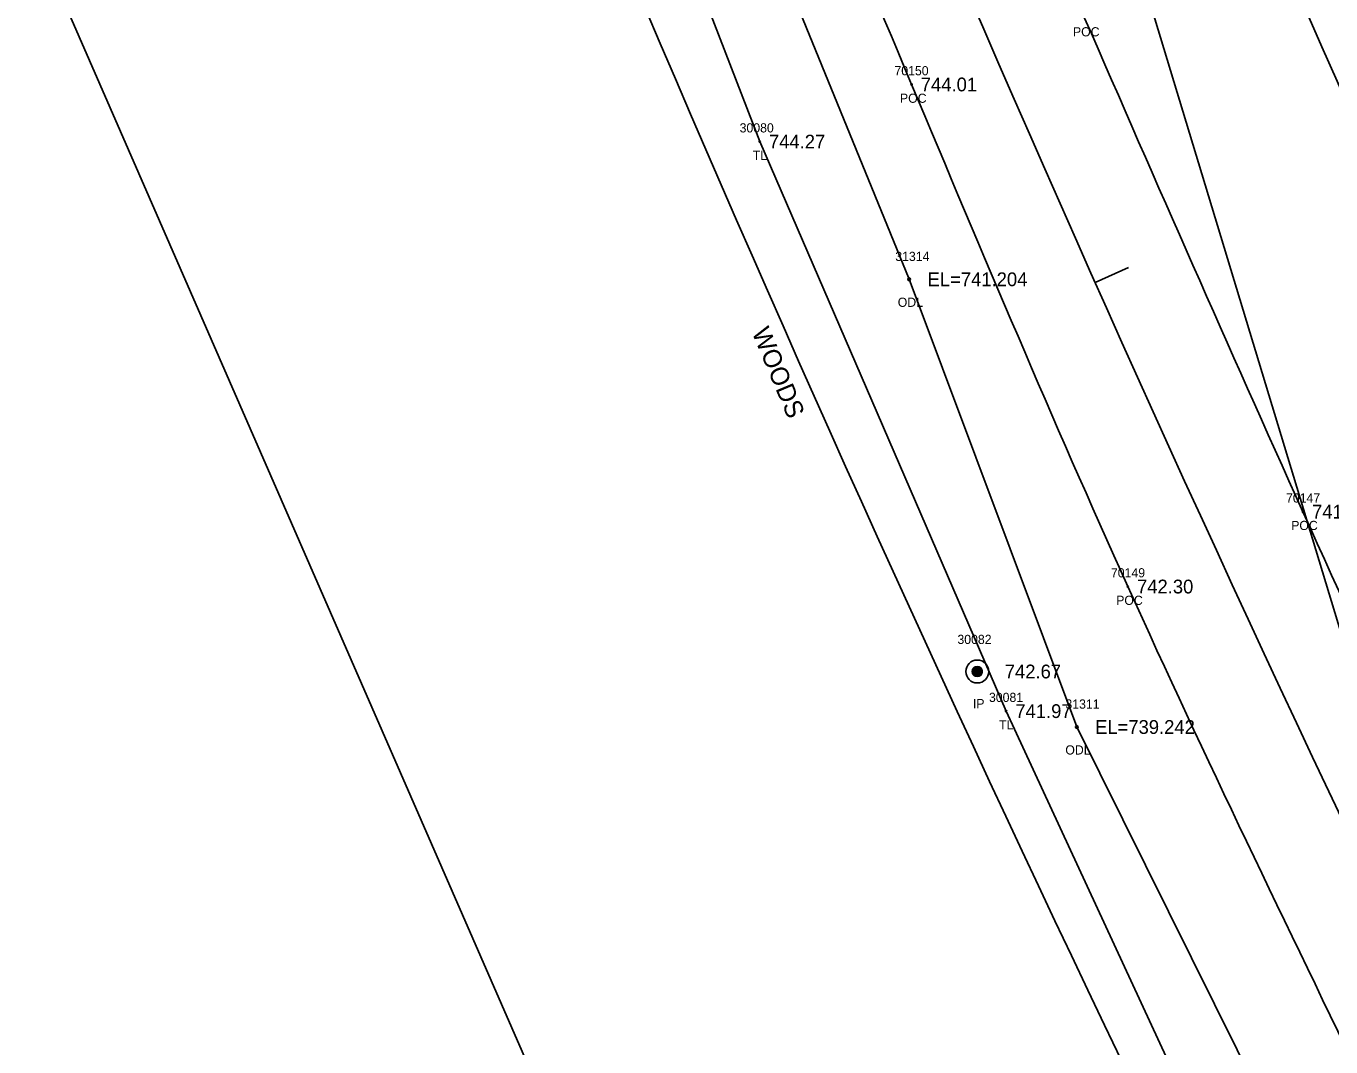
# Model space of a CAD drawing. Extents: x 1375131 to 1378678, y 999028 to 1004053.
# Drawn here: x 1376731 to 1376873.2, y 1002476.7 to 1002588 of the extents above; entities that cross this region are included whole.
import ezdxf

# ---------------------------------------------------------------- set-up
doc = ezdxf.new("R2010")
doc.units = 0
for name, color, linetype in [('RD_EX_DV_Prop', 7, 'Continuous'), ('RD_EX_DV_Prop_txCode', 7, 'Continuous'), ('RD_EX_DV_PropPin', 7, 'Continuous'), ('RD_EX_H2O', 7, 'Continuous'), ('RD_EX_H2O_txCode', 7, 'Continuous'), ('RD_EX_Road', 7, 'Continuous'), ('RD_EX_Road_txCode', 7, 'Continuous'), ('RD_EX_RW', 7, 'Continuous'), ('RD_EX_SU_Elec', 7, 'Continuous'), ('RD_EX_TX_DV_Prop_ELEV', 7, 'Continuous'), ('RD_EX_TX_H2O_ELEV', 7, 'Continuous'), ('RD_EX_TX_Road_ELEV', 7, 'Continuous'), ('RD_EX_TX_VEG_ELEV', 7, 'Continuous'), ('RD_EX_VEG', 7, 'Continuous'), ('RD_EX_VEG_txCode', 7, 'Continuous'), ('RD_HC_Cl', 7, 'Continuous'), ('RD_HC_Data_Tic', 7, 'Continuous'), ('RD_SMD_Locator', 7, 'Continuous'), ('RD_TX_Misc2', 7, 'Continuous')]:
    doc.layers.add(name, color=color, linetype=linetype)

msp = doc.modelspace()

# ---------------------------------------------------------------- linework, layer by layer
at = {"layer": 'RD_EX_DV_Prop'}
msp.add_lwpolyline([(1376724.42, 1002117.06), (1376637.57, 1002230.63), (1376389.38, 1002558.79), (1376664.3, 1002769.81), (1376707.09, 1002654.77), (1376824.56, 1002385.67), (1376921.89, 1002216.69), (1376947.76, 1002098.6)], dxfattribs=at)
at = {"layer": 'RD_EX_DV_PropPin'}
for p, q in [((1376834.35, 1002517.16), (1376834.35, 1002518.1)), ((1376834.38, 1002517.15), (1376834.38, 1002518.11)), ((1376834.4, 1002517.13), (1376834.4, 1002518.12)), ((1376834.43, 1002517.12), (1376834.43, 1002518.13)), ((1376834.45, 1002517.11), (1376834.45, 1002518.14)), ((1376834.48, 1002517.11), (1376834.48, 1002518.15)), ((1376834.5, 1002517.1), (1376834.5, 1002518.16)), ((1376834.53, 1002517.09), (1376834.53, 1002518.16)), ((1376834.55, 1002517.09), (1376834.55, 1002518.17)), ((1376834.58, 1002517.09), (1376834.58, 1002518.17)), ((1376834.6, 1002517.09), (1376834.6, 1002518.17)), ((1376834.63, 1002517.09), (1376834.63, 1002518.17)), ((1376834.65, 1002517.09), (1376834.65, 1002518.17)), ((1376834.68, 1002517.09), (1376834.68, 1002518.17)), ((1376834.7, 1002517.09), (1376834.7, 1002518.17)), ((1376834.73, 1002517.09), (1376834.73, 1002518.16)), ((1376834.75, 1002517.1), (1376834.75, 1002518.16)), ((1376834.78, 1002517.11), (1376834.78, 1002518.15)), ((1376834.8, 1002517.11), (1376834.8, 1002518.14)), ((1376834.83, 1002517.12), (1376834.83, 1002518.13)), ((1376834.85, 1002517.13), (1376834.85, 1002518.12)), ((1376834.88, 1002517.15), (1376834.88, 1002518.11)), ((1376834.9, 1002517.16), (1376834.9, 1002518.1)), ((1376834.1, 1002517.49), (1376834.1, 1002517.77)), ((1376834.13, 1002517.42), (1376834.13, 1002517.84)), ((1376834.15, 1002517.37), (1376834.15, 1002517.89)), ((1376834.18, 1002517.32), (1376834.18, 1002517.93)), ((1376834.2, 1002517.29), (1376834.2, 1002517.97)), ((1376834.23, 1002517.26), (1376834.23, 1002518)), ((1376834.25, 1002517.24), (1376834.25, 1002518.02)), ((1376834.28, 1002517.21), (1376834.28, 1002518.04)), ((1376834.3, 1002517.19), (1376834.3, 1002518.06)), ((1376834.33, 1002517.18), (1376834.33, 1002518.08)), ((1376834.93, 1002517.18), (1376834.93, 1002518.08)), ((1376834.95, 1002517.19), (1376834.95, 1002518.06)), ((1376834.98, 1002517.21), (1376834.98, 1002518.04)), ((1376835, 1002517.24), (1376835, 1002518.02)), ((1376835.03, 1002517.26), (1376835.03, 1002518)), ((1376835.05, 1002517.29), (1376835.05, 1002517.97)), ((1376835.08, 1002517.32), (1376835.08, 1002517.93)), ((1376835.1, 1002517.37), (1376835.1, 1002517.89)), ((1376835.13, 1002517.42), (1376835.13, 1002517.84)), ((1376835.15, 1002517.49), (1376835.15, 1002517.77))]:
    msp.add_line(p, q, dxfattribs=at)
for radius in [1.25, 0.543]:
    msp.add_circle((1376834.63, 1002517.63), radius, dxfattribs=at)
at = {"layer": 'RD_EX_H2O'}
msp.add_lwpolyline([(1376884.04, 1002432.1), (1376867.96, 1002466.27), (1376845.47, 1002511.58), (1376827.22, 1002560.38), (1376806.48, 1002611.18), (1376788.41, 1002651.65), (1376772.82, 1002694.38), (1376753.28, 1002747.21), (1376736.65, 1002792.89), (1376719.2, 1002838.91), (1376701.08, 1002887.18), (1376684.58, 1002932.85), (1376667.2, 1002979.87)], dxfattribs=at)
at = {"layer": 'RD_EX_Road'}
for points in [[(1377013.31, 1002264.91), (1376982.81, 1002315.68), (1376952.47, 1002370.34), (1376923.17, 1002424.32), (1376895.64, 1002480.03), (1376870.11, 1002535.05), (1376846.33, 1002588.86), (1376822.29, 1002645.03), (1376786.56, 1002736.46)], [(1376994.75, 1002253.91), (1376964.91, 1002306.46), (1376934.4, 1002359.99), (1376904.77, 1002415.49), (1376877.27, 1002471.51), (1376851.04, 1002526.89), (1376827.48, 1002581.62), (1376804.19, 1002637.82), (1376768.46, 1002728.84)]]:
    msp.add_spline(points, degree=3, dxfattribs=at)
at = {"layer": 'RD_EX_RW'}
for radius in [2767, 2833]:
    msp.add_arc((1379404.86, 1003700.11), radius, 200.26995, 211.13117, dxfattribs=at)
at = {"layer": 'RD_EX_SU_Elec'}
msp.add_line((1376829.24, 1002670.59), (1376932.6, 1002329.07), dxfattribs=at)
at = {"layer": 'RD_EX_VEG'}
msp.add_lwpolyline([(1376822.36, 1002383.95), (1376864.26, 1002456.06), (1376837.78, 1002513.31), (1376810.93, 1002575.39), (1376788.96, 1002632.35), (1376765.83, 1002686.46), (1376747.01, 1002742.76), (1376726.94, 1002799.92), (1376678.97, 1002911.63), (1376653.9, 1002974.89)], dxfattribs=at)
at = {"layer": 'RD_HC_Cl'}
msp.add_arc((1379404.86, 1003700.11), 2800, 200.26995, 211.13117, dxfattribs=at)
at = {"layer": 'RD_HC_Data_Tic'}
msp.add_line((1376847.47, 1002560.04), (1376851.12, 1002561.67), dxfattribs=at)
at = {"layer": 'RD_SMD_Locator'}
for centre, radius in [((1376827.48, 1002581.62), 0.075), ((1376810.93, 1002575.39), 0.075), ((1376827.22, 1002560.38), 0.15), ((1376870.11, 1002535.05), 0.075), ((1376851.04, 1002526.89), 0.075), ((1376834.63, 1002517.63), 0.075), ((1376837.78, 1002513.31), 0.075), ((1376845.47, 1002511.58), 0.15)]:
    msp.add_circle(centre, radius, dxfattribs=at)

# ---------------------------------------------------------------- texts
at = {"layer": 'RD_EX_DV_Prop_txCode'}
for s, p in [('30082', (1376832.47, 1002520.63)), ('IP', (1376834.16, 1002513.63))]:
    msp.add_text(s, height=1, dxfattribs=at).set_placement(p)
at = {"layer": 'RD_EX_H2O_txCode'}
for s, p in [('31314', (1376825.7, 1002562.38)), ('ODL', (1376825.97, 1002557.38)), ('31311', (1376844.24, 1002513.58)), ('ODL', (1376844.23, 1002508.58))]:
    msp.add_text(s, height=1, dxfattribs=at).set_placement(p)
at = {"layer": 'RD_EX_Road_txCode'}
for s, p in [('POC', (1376845.06, 1002586.86)), ('70150', (1376825.61, 1002582.62)), ('POC', (1376826.21, 1002579.62)), ('70147', (1376868.28, 1002536.05)), ('POC', (1376868.84, 1002533.05)), ('70149', (1376849.2, 1002527.89)), ('POC', (1376849.77, 1002524.89))]:
    msp.add_text(s, height=1, dxfattribs=at).set_placement(p)
at = {"layer": 'RD_EX_TX_DV_Prop_ELEV'}
msp.add_text('742.67', height=1.5, dxfattribs=at).set_placement((1376837.63, 1002516.88))
at = {"layer": 'RD_EX_TX_H2O_ELEV'}
for s, p in [('EL=741.204', (1376829.22, 1002559.63)), ('EL=739.242', (1376847.47, 1002510.83))]:
    msp.add_text(s, height=1.5, dxfattribs=at).set_placement(p)
at = {"layer": 'RD_EX_TX_Road_ELEV'}
for s, p in [('744.01', (1376828.48, 1002580.87)), ('741.54', (1376871.11, 1002534.3)), ('742.30', (1376852.04, 1002526.14))]:
    msp.add_text(s, height=1.5, dxfattribs=at).set_placement(p)
at = {"layer": 'RD_EX_TX_VEG_ELEV'}
for s, p in [('744.27', (1376811.93, 1002574.64)), ('741.97', (1376838.78, 1002512.56))]:
    msp.add_text(s, height=1.5, dxfattribs=at).set_placement(p)
at = {"layer": 'RD_EX_VEG_txCode'}
for s, p in [('30080', (1376808.74, 1002576.39)), ('TL', (1376810.16, 1002573.39)), ('30081', (1376835.91, 1002514.31)), ('TL', (1376837.01, 1002511.31))]:
    msp.add_text(s, height=1, dxfattribs=at).set_placement(p)
at = {"layer": 'RD_TX_Misc2'}
msp.add_text('WOODS', height=2, rotation=292.755, dxfattribs=at).set_placement((1376810.03, 1002554.64))

doc.saveas('drawing.dxf')
